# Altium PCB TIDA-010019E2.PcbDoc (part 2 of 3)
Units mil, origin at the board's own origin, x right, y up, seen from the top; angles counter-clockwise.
Board outline 3159.64 x 4813.18 mil, 2 copper layers (Top Layer, Bottom Layer), stack 62 mil thick; 303 components, 177 nets, 861 pads, 1443 vias.
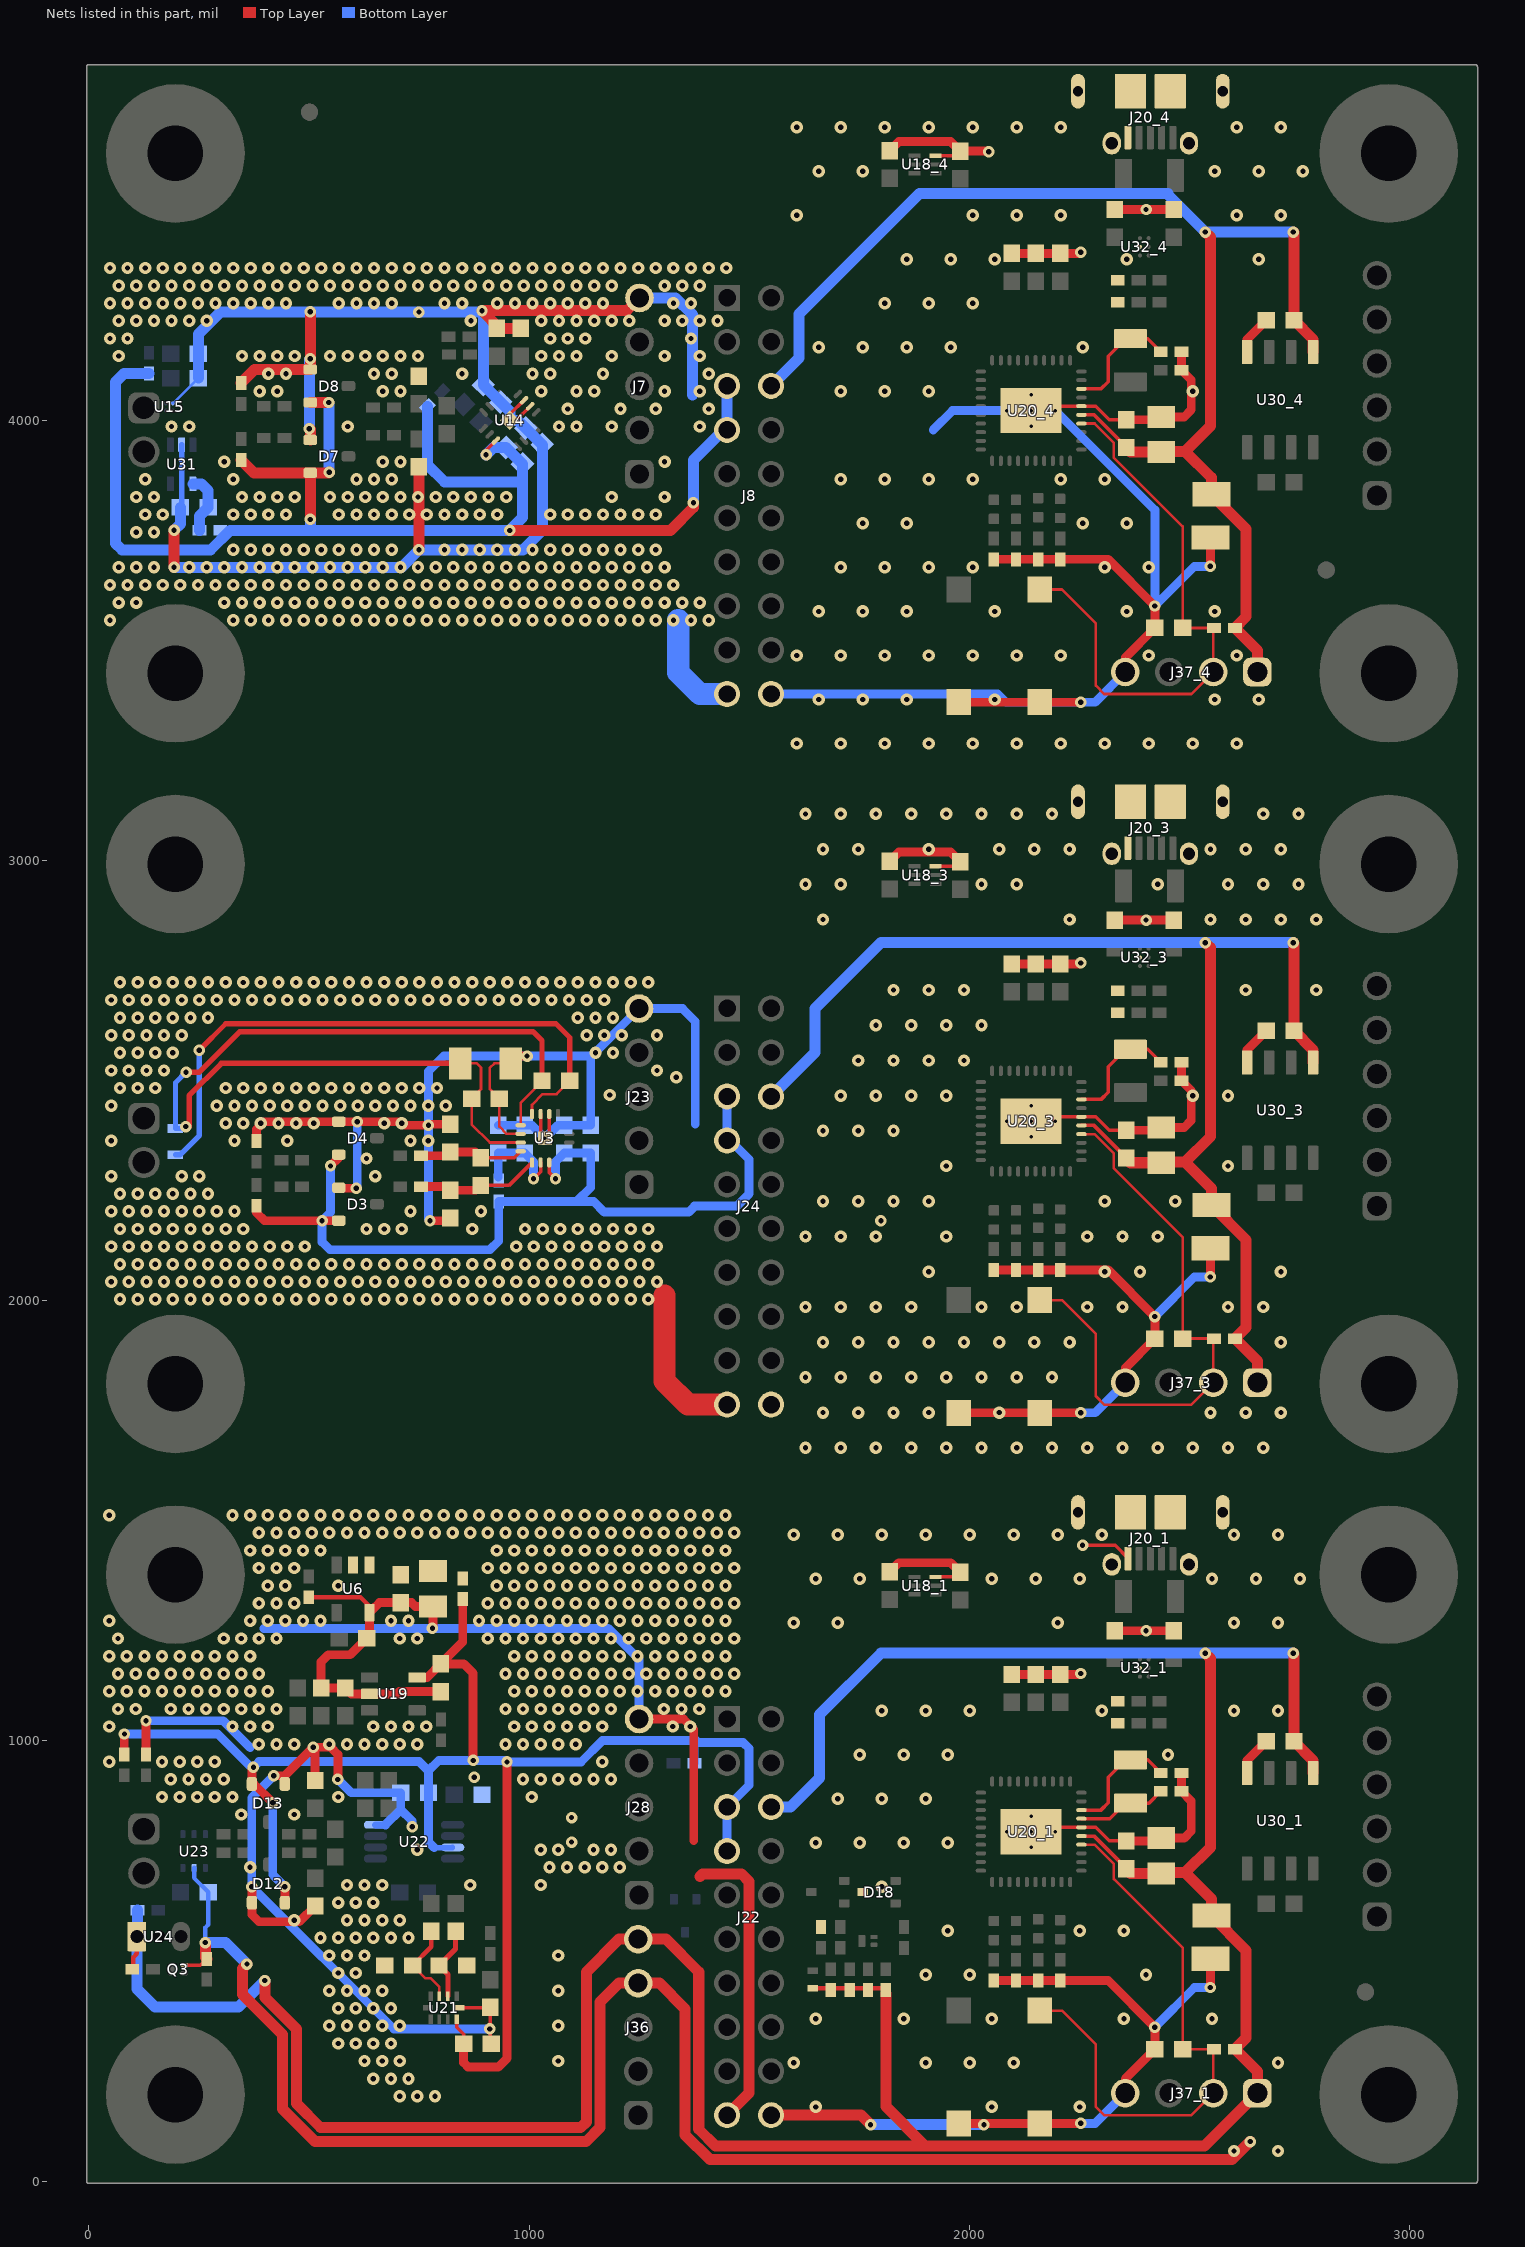
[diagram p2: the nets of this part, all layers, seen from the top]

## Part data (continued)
D16 D17 D18: library part CMP-0028438-2, "Diode, Schottky, 40 V, 0.2 A, SOT-323", Manufacturer="Diodes Inc.", Value1=0.2A, Value2=0.9V
F1_1 F1_3 F1_4: library part CMP-0081903-1, "Fuse, 0.05 A, 60 VDC, SMD", Irating_A=50mA, Manufacturer="Bel Fuse", Supplier Part Number 1=507-1793-1-ND
FID1 FID2 FID3 FID4 FID5 FID6: library part CMP-0077181-1, "Fiducial mark.  There is nothing to buy or mount.", Manufacturer=N/A
H9 H10 H11 H12 H17 H18 H19 H20 H37 H38 H39 H40: library part CMP-0003617-1, "Machine Screw, Round, #4-40 x 1/4, Nylon, Philips panhead", Manufacturer="B&F Fastener Supply", Supplier Part Number 1=H542-ND
H13 H14 H15 H16 H21 H22 H23 H24 H45 H46 H47 H48: library part CMP-0003610-1, "Standoff, Hex, 0.5\"L #4-40 Nylon", Manufacturer=Keystone, Supplier Part Number 1=36-1902C-ND
J2 J5 J31: library part CMP-0082072-1, "Receptacle, 2.54mm, 2x1, Tin, R/A, TH", Color=Green, Current_A=6A, Manufacturer="Wurth Elektronik", Voltage_V=150V
J7 J23 J28 J36: library part CMP-0084909-1, "Header, 2.54mm, 5x1, Gold, TH", Color=Black, Current_A=3A, Manufacturer="Wurth Elektronik", Voltage_V=250V
J8 J22 J24: library part CMP-0054591-2, "Header, 2.54mm, 10x2, Gold, TH", Color=Black, Manufacturer="Sullins Connector Solutions", Supplier Part Number 1=S2011EC-10-ND
J20_1 J20_3 J20_4: library part CMP-0055301-1, "Connector, Receptacle, Micro-USB Type AB, R/A, Bottom Mount SMT", Manufacturer=Molex, Supplier Part Number 1=WM17143CT-ND
J37_1 J37_3 J37_4: library part CMP-0054798-2, "Header, 2.54 mm, 4x1, Gold, TH", Color=Black, Manufacturer="Wurth Elektronik", Supplier Part Number 1=732-5317-ND
J39_1 J39_3 J39_4: library part CMP-0054801-2, "Header, 2.54 mm, 6x1, Gold, TH", Color=Black, Manufacturer="Wurth Elektronik", Supplier Part Number 1=732-5319-ND
LBL1 LBL3 LBL4: library part CMP-0003625-1, "Thermal Transfer Printable Labels, 0.650\" W x 0.200\" H - 10,000 per roll", Manufacturer=Brady, Supplier Part Number 1=97C5133
Logo1 Logo2 Logo16: library part CMP-0074838-1, "Texas Instrument Corporate Signature"
Logo3 Logo5 Logo17: library part CMP-0074847-1, "FCC_disclaimer"
Logo4 Logo6 Logo18: library part CMP-0074769-1
Q3 Q6: library part CMP-0082028-2, "Transistor, NPN, 65 V, 0.1 A, AEC-Q101, 1x0.6mm", Manufacturer="Diodes Inc.", Value1="0.1 A", Value2=450
R4 R9 R44 R50 R70 R85 R120: library part CMP-0026827-3, "RES, 10, 5%, 0.063 W, AEC-Q200 Grade 0, 0402", Manufacturer=Vishay-Dale, Power_W=63mW, Supplier Part Number 1=541-10JCT-ND, TempCo="200 ppm/C", Tolerance_%=5%, Value2=0.063W, Value_Code=10R0, ValueDisplayed=10
R6 R52: library part CMP-0025950-3, "RES, 100 k, 1%, 0.063 W, AEC-Q200 Grade 0, 0402", Manufacturer=Vishay-Dale, Power_W=63mW, Supplier Part Number 1=541-100KLCT-ND, TempCo="100 ppm/C", Tolerance_%=1%, Value2=0.063W, Value_Code=100k
R8: library part CMP-0085900-1, "RES, 1.00 M, 1%, 0.1 W, AEC-Q200 Grade 0, 0603", Manufacturer="Stackpole Electronics Inc", Power_W=100mW, TempCo="100 ppm/C", Tolerance_%=1%, Value2=0.1W, Value_Code=1M00, ValueDisplayed=1.00M
R10 R15 R45 R51 R73 R83: library part CMP-0026245-2, "RES, 2.00 M, 1%, 0.063 W, AEC-Q200 Grade 0, 0402", Manufacturer=Vishay-Dale, Power_W=63mW, Supplier Part Number 1=541-2.00MLCT-ND, TempCo="100 ppm/C", Tolerance_%=1%, Value2=0.063W, Value_Code=2M00, ValueDisplayed=2.00M
R11 R12 R13 R14 R46 R47 R48 R49 R76 R81: library part CMP-0026402-2, "RES, 499, 1%, 0.063 W, AEC-Q200 Grade 0, 0402", Manufacturer=Vishay-Dale, Power_W=63mW, Supplier Part Number 1=541-499LCT-ND, TempCo="100 ppm/C", Tolerance_%=1%, Value2=0.063W, Value_Code=499R, ValueDisplayed=499
R16: library part CMP-0018789-2, "RES, 3.24 k, 0.1%, 0.333 W, 1206", Manufacturer="TT Electronics/IRC", Power_W=333mW, Supplier Part Number 1=66-PFC12L3.24K-B, TempCo="10 ppm/C", Tolerance_%=0.1%, Value2=0.333W, Value_Code=3k24, ValueDisplayed=3.24k
R25_1 R25_3 R25_4: library part CMP-0026935-3, "RES, 47 k, 5%, 0.063 W, AEC-Q200 Grade 0, 0402", Manufacturer=Vishay-Dale, Power_W=63mW, Supplier Part Number 1=541-47KJCT-ND, TempCo="200 ppm/C", Tolerance_%=5%, Value2=0.063W, Value_Code=47k0, ValueDisplayed=47k
R27_1 R27_3 R27_4 R55_1 R55_3 R55_4 R56_1 R56_3 R56_4 R57_1 R57_3 R57_4: library part CMP-0026333-2, "RES, 3.32 k, 1%, 0.063 W, AEC-Q200 Grade 0, 0402", Manufacturer=Vishay-Dale, Power_W=63mW, Supplier Part Number 1=541-3.32KLCT-ND, TempCo="100 ppm/C", Tolerance_%=1%, Value2=0.063W, Value_Code=3k32, ValueDisplayed=3.32k
R65_1 R65_3 R65_4 R66_1 R66_3 R66_4 R109_1 R109_3 R109_4: library part CMP-0022109-5, "RES, 1.00 k, 1%, 0.1 W, AEC-Q200 Grade 0, 0603", Manufacturer=Vishay-Dale, Power_W=100mW, Supplier Part Number 1=541-1.00KHCT-ND, TempCo="100 ppm/C", Tolerance_%=1%, Value2=0.1W, Value_Code=1k00, ValueDisplayed=1.00k
R71: library part CMP-0026938-5, "RES, 4.7 k, 5%, 0.063 W, AEC-Q200 Grade 0, 0402", Manufacturer=Vishay-Dale, Power_W=63mW, Supplier Part Number 1=541-4.7KJCT-ND, TempCo="200 ppm/C", Tolerance_%=5%, Value2=0.063W, Value_Code=4k70, ValueDisplayed=4.7k
R72: library part CMP-0022441-4, "RES, 487 k, 1%, 0.1 W, AEC-Q200 Grade 0, 0603", Manufacturer=Vishay-Dale, Power_W=100mW, Supplier Part Number 1=541-487KHCT-ND, TempCo="100 ppm/C", Tolerance_%=1%, Value2=0.1W, Value_Code=487k
R74 R75 R78 R80: library part CMP-0021998-4, "RES, 10.0 k, 1%, 0.1 W, AEC-Q200 Grade 0, 0603", Manufacturer=Vishay-Dale, Power_W=100mW, Supplier Part Number 1=541-10.0KHCT-ND, TempCo="100 ppm/C", Tolerance_%=1%, Value2=0.1W, Value_Code=10k0, ValueDisplayed=10.0k
R77 R82: library part CMP-0025958-3, "RES, 10.0 k, 1%, 0.063 W, AEC-Q200 Grade 0, 0402", Manufacturer=Vishay-Dale, Power_W=63mW, Supplier Part Number 1=541-10.0KLCT-ND, TempCo="100 ppm/C", Tolerance_%=1%, Value2=0.063W, Value_Code=10k0, ValueDisplayed=10.0k
R79: library part CMP-0022372-4, "RES, 3.09 k, 1%, 0.1 W, AEC-Q200 Grade 0, 0603", Manufacturer=Vishay-Dale, Power_W=100mW, Supplier Part Number 1=541-3.09KHCT-ND, TempCo="100 ppm/C", Tolerance_%=1%, Value2=0.1W, Value_Code=3k09, ValueDisplayed=3.09k
R84: library part CMP-0026915-3, "RES, 39 k, 5%, 0.063 W, AEC-Q200 Grade 0, 0402", Manufacturer=Vishay-Dale, Power_W=63mW, Supplier Part Number 1=541-39KJCT-ND, TempCo="200 ppm/C", Tolerance_%=5%, Value2=0.063W, Value_Code=39k0, ValueDisplayed=39k
R86: library part CMP-0026963-3, "RES, 68 k, 5%, 0.063 W, AEC-Q200 Grade 0, 0402", Manufacturer=Vishay-Dale, Power_W=63mW, Supplier Part Number 1=541-68KJCT-ND, TempCo="200 ppm/C", Tolerance_%=5%, Value2=0.063W, Value_Code=68k0, ValueDisplayed=68k
R87: library part CMP-0026966-5, "RES, 6.8 k, 5%, 0.063 W, AEC-Q200 Grade 0, 0402", Manufacturer=Vishay-Dale, Power_W=63mW, Supplier Part Number 1=541-6.8KJCT-ND, TempCo="200 ppm/C", Tolerance_%=5%, Value2=0.063W, Value_Code=6k80, ValueDisplayed=6.8k
R110: library part CMP-0026193-2, "RES, 249 k, 1%, 0.063 W, AEC-Q200 Grade 0, 0402", Manufacturer=Vishay-Dale, Power_W=63mW, Supplier Part Number 1=541-249KLCT-ND, TempCo="100 ppm/C", Tolerance_%=1%, Value2=0.063W, Value_Code=249k
R111 R112 R113: library part CMP-0026823-3, "RES, 100 k, 5%, 0.063 W, AEC-Q200 Grade 0, 0402", Manufacturer=Vishay-Dale, Power_W=63mW, Supplier Part Number 1=541-100KJCT-ND, TempCo="200 ppm/C", Tolerance_%=5%, Value2=0.063W, Value_Code=100k
R114: library part CMP-0026852-3, "RES, 1.0 k, 5%, 0.063 W, AEC-Q200 Grade 0, 0402", Manufacturer=Vishay-Dale, Power_W=63mW, Supplier Part Number 1=541-1.0KJCT-ND, TempCo="200 ppm/C", Tolerance_%=5%, Value2=0.063W, Value_Code=1k00, ValueDisplayed=1.0k
R115: library part CMP-0026490-2, "RES, 61.9 k, 1%, 0.063 W, AEC-Q200 Grade 0, 0402", Manufacturer=Vishay-Dale, Power_W=63mW, Supplier Part Number 1=541-61.9KLCT-ND, TempCo="100 ppm/C", Tolerance_%=1%, Value2=0.063W, Value_Code=61k9, ValueDisplayed=61.9k
R116_1 R116_3 R116_4 R117_1 R117_3 R117_4 R118_1 R118_3 R118_4 R119_1 R119_3 R119_4 R121: library part CMP-0081856-1, "RES, 0, 0%, 0.2 W, AEC-Q200 Grade 0, 0402", Manufacturer=Vishay-Dale, Power_W=200mW, Supplier Part Number 1=541-0.0YBTR-ND, Tolerance_%=0%, Value2=0.2W, Value_Code=0
RT2: library part CMP-0001709-3, "Temperature Sensor 100 ohm, SMD", Manufacturer=Vishay/Beyschlag, Supplier Part Number 1=PTS0603100CT-ND
S1_1 S1_3 S1_4 S2_1 S2_3 S2_4: library part CMP-0002196-2, "Switch, Tactile, SPST, 12 V, SMD", CurrentRating_mA=50A, Manufacturer="Wurth Elektronik", Supplier Part Number 1=31T8978
SH-J1 SH-J2 SH-J3 SH-J4 SH-J5 SH-J6 SH-J7 SH-J8 SH-J9 SH-J10 SH-J11 SH-J12 SH-J13 SH-J14 SH-J15 SH-J16 SH-J17 SH-J18 SH-J19 SH-J20 SH-J21: library part CMP-0003761-2, "Shunt, 2.54mm, Gold, Black", Manufacturer="Wurth Elektronik", Supplier Part Number 1=732-2678-ND
TP1_1 TP1_3 TP1_4 TP2_1 TP2_3 TP2_4: library part CMP-0003968-1, "Test Point, SMT", Manufacturer=Harwin, Supplier Part Number 1=952-2664-1-ND
U3 U14: library part CMP-0078503-1, "16-Bit, 4-Channel, 2-kSPS, Delta-Sigma ADC with UART Interface, RTE0016D (WQFN-16)", Alternate Manufacturer="Texas Instruments", Alternate PartNumber=ADS112U04IRTER
U6: library part CMP-0082641-1, "Low-Drift Low-Power Small-Footprint Series Voltage Reference With Clean Start, DBV0005A (SOT-23-5)", Alternate Manufacturer="Texas Instruments", Operating Temperature Range="-40 to 125 C", Rating=Catalog
U15: library part CMP-0066231-1, "+/-0.1degC Precision Analog Temperature Sensor, YFQ0004ACAC (DSBGA-4)", Alternate Manufacturer="Texas Instruments", Alternate PartNumber=LMT70YFQT
U18_1 U18_3 U18_4: library part CMP-0036117-3, "250-mA, Ultralow IQ, Fast Transient Response, RF Low-Dropout Linear Regulator,  DSE0006A (WSON-6)", Manufacturer="Texas Instruments", Operating Temperature Range="-40 to 125 C", Rating=Catalog
U19: library part CMP-0065082-2, "700nA, Precision Zero-Drift Amplifier, DBV0005A (SOT-23-5)", Alternate Manufacturer="Texas Instruments", Alternate PartNumber=LPV821DBVT
U20_1 U20_3 U20_4: library part CMP-0081780-1, "Mixed-Signal Microcontroller, RHA0040E (VQFN-40)", Alternate Manufacturer="Texas Instruments", Alternate PartNumber=MSP430FR2355TRHAT, Operating Temperature Range="-40 to 105 C", Rating=Catalog
U21: library part CMP-0065258-3, "Nanopower, Ultra-Small Size, Sensor Monitor with I2C Interface and Alert Output, RUG0010A (X2QFN-10)", Alternate Manufacturer="Texas Instruments", Alternate PartNumber=ADS7142IRUGT
U22: library part CMP-0081218-1, "Micro-Power (50 µA), Zero-Drift, Rail-to-Rail-Out Instrumentation Amplifier, DGK0008A (VSSOP-8)", Alternate Manufacturer="Texas Instruments", Alternate PartNumber=INA317IDGKT
U23: library part CMP-0081990-1, "High-Accuracy, Low-Power, Digital Temperature Sensor With SMBus- and I2C-Compatible Interface, DRV0006B (WSON-6)", Alternate Manufacturer="Texas Instruments", Alternate PartNumber=TMP117AIDRVT, Operating Temperature Range="-55 to 150 C"
U24: library part CMP-0076503-2, "0.5degC Accurate 2-pin Temperature Sensor with a Pulse Train Interface, LPG0002A (TO-92-2)", Alternate Manufacturer="Texas Instruments"
U30_1 U30_3 U30_4: library part CMP-0085670-1, "High Speed, Robust EMC Reinforced Dual-Channel Digital Isolator, D0008B (SOIC-8)", Alternate Manufacturer="Texas Instruments", Alternate PartNumber=ISO7721DR, Operating Temperature Range="-55 to 125 C", Rating=Catalog
U31: library part CMP-0013250-3, "TMP235DCK, DCK0005A (SOT-5)", Manufacturer="Texas Instruments"
U32_1 U32_3 U32_4: library part CMP-0034332-1, "Ultra-Low Power, Low Input Voltage, Current Limited Load Switch, 300 mOhms rDS(On), -40 to 85 degC, 6-pin DSBGA (YZP), Green (RoHS & no Sb/Br)", Adjustable Current Limit(Min)(A)="0.155, 0.07, 0.03", Manufacturer="Texas Instruments"
Y1_1 Y1_3 Y1_4: library part CMP-0078856-1, "Crystal, 32.768 KHz, 20 ppm, SMD", Frequency_Fixed=32.768kHz, Frequency Tolerance="20 ppm", Manufacturer="ECS Inc.", Supplier Part Number 1=XC1617CT-ND
ZZ1: library part CMP-0003616-3
ZZ2: library part CMP-0077236-1
ZZ3: library part CMP-0077237-1
ZZ4: library part CMP-0077238-1

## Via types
v1: diameter 28, hole 12, Top Layer to Bottom Layer, tented both sides, 1305 vias
v2: diameter 26, hole 12, Top Layer to Bottom Layer, tented both sides, 120 vias
v3: diameter 19.68, hole 7.87, Top Layer to Bottom Layer, tented both sides, 17 vias
v4: diameter 26, hole 12, Top Layer to Bottom Layer, 1 vias

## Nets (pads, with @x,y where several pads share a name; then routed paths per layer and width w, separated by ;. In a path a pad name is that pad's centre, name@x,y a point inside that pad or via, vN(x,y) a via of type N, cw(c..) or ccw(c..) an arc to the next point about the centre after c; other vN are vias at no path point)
3.3V_1: C65_1.1 C66_1.1 C86_1.1 C87.1 J22.6 J36.5 J37_1.1 R25_1.2 R84.2 R85.1 R86.2 R110.2 R111.2 R112.2 TP2_1.1 U20_1.5 U24.1 U30_1.1 | length 7580.9
  Top Layer w8: U20_1.5@2254.88,784.1 2283.54,784.1 2356.22,711.42 C66_1.1@2356.22,710.01
  Top Layer w10: R86.2@101.38,481.54 101.38,508.68 109.15,516.46 U24.1@109.15,555.83 ; R84.2@1645,437.91 1807.14,437.91 C87.1@1810.76,434.29
  Top Layer w25: v2(400,455.83) 400,417.46 471.5,345.96 471.5,176.9 526.9,121.5 1117.16,121.5 1130.5,134.84 1130.5,475.54 1204.79,549.83 J36.5@1248,549.83 1310.8,549.83 1385.59,475.04 1385.59,118.03 1423.62,80 1900,80 ; C87.1@1810.76,426.38 1810.76,169.24 1900,80 ; C66_1.1@2356.22,710.01 2366.85,699.38 C65_1.1@2436.22,699.38 2437.87,701.03 2490.28,701.03 ; v2(2536.22,1199.38) 2547.76,1187.84 2547.76,758.51 2490.28,701.03 ; v2(2736.22,1199.38) 2737.72,1197.88 C86_1.1@2737.72,999.38 2781.22,955.87 U30_1.1@2781.22,927.07 ; 1900,80 2534.51,80 J37_1.1@2654.51,200 2654.51,249.11 R25_1.2@2603.62,300 2629.21,325.59 2629.21,524.39 TP2_1.1@2550,603.6 2550,641.31 2490.28,701.03
  Bottom Layer w25: R85.1@110.53,615.83 110.53,557.2 U24.1@109.15,555.83 109.15,436.76 150.09,395.83 340,395.83 v2(400,455.83) ; J22.6@1550,850 1594.17,850 1660,915.83 1660,1060 1799.38,1199.38 v2(2536.22,1199.38) v2(2736.22,1199.38)
3.3V_3: C65_3.1 C66_3.1 C86_3.1 J24.6 J37_3.1 R25_3.2 TP2_3.1 U20_3.5 U30_3.1 | length 3069.7
  Top Layer w8: U20_3.5@2254.88,2398.27 2283.54,2398.27 2356.22,2325.59 C66_3.1@2356.22,2324.18
  Top Layer w25: C66_3.1@2356.22,2324.18 2366.85,2313.55 C65_3.1@2436.22,2313.55 2437.87,2315.2 2490.28,2315.2 ; v2(2536.22,2813.55) 2547.76,2802.02 2547.76,2372.68 2490.28,2315.2 ; J37_3.1@2654.51,1814.17 2654.51,1863.28 R25_3.2@2603.62,1914.17 2629.21,1939.76 2629.21,2138.56 TP2_3.1@2550,2217.77 2550,2255.49 2490.28,2315.2 ; v2(2736.22,2813.55) 2737.72,2812.06 C86_3.1@2737.72,2613.55 2781.22,2570.05 U30_3.1@2781.22,2541.25
  Bottom Layer w25: J24.6@1550,2464.17 1650,2564.17 1650,2664.17 1799.38,2813.55 v2(2536.22,2813.55) v2(2736.22,2813.55)
3.3V_4: C65_4.1 C66_4.1 C86_4.1 J8.6 J37_4.1 R25_4.2 TP2_4.1 U20_4.5 U30_4.1 | length 3143.8
  Top Layer w8: U20_4.5@2254.88,4012.44 2283.54,4012.44 2356.21,3939.76 C66_4.1@2356.21,3938.35
  Top Layer w25: C66_4.1@2356.21,3938.35 2366.84,3927.72 C65_4.1@2436.21,3927.72 2437.87,3929.37 2490.27,3929.37 ; v2(2536.21,4427.72) 2547.75,4416.18 2547.75,3986.85 2490.27,3929.37 ; J37_4.1@2654.51,3428.34 2654.51,3477.45 R25_4.2@2603.62,3528.34 2629.21,3553.93 2629.21,3752.73 TP2_4.1@2549.99,3831.94 2549.99,3869.65 2490.27,3929.37 ; v2(2736.21,4427.72) 2737.71,4426.22 C86_4.1@2737.71,4227.72 2781.21,4184.22 U30_4.1@2781.21,4155.42
  Bottom Layer w25: J8.6@1550,4078.35 1613.27,4141.62 1613.27,4241.62 1887.11,4515.46 2451.02,4515.46 2451.02,4512.91 v2(2536.21,4427.72) v2(2736.21,4427.72)
3.3V_7: C51.1 C54.1 C68.1 D12.2 D13.2 J22.5 J22.7 R4.2 R73.2 R113.2 U19.5 U21.9 U22.7 | length 3827.5
  Top Layer w8: U21.9@835.56,367.5 835.56,350.04 851.5,334.1 C54.1@851.5,312.2
  Top Layer w20: R73.2@80.41,969.45 80.41,1015.23 v2(81.01,1015.83) ; v2(373.99,940.35) 370.6,936.96 D13.2@370.6,902.36 375.17,902.36 v2(418,859.53) ; D12.2@445.4,632.68 v2(445.4,668.93) ; U19.5@745.79,1144.27 768.65,1144.27 C51.1@799.61,1175.22 ; R4.2@849.56,1322.2 849.56,1225.18 C51.1@799.61,1175.22 ; C54.1@851.5,312.2 851.5,269.51 861.73,259.27 930.24,259.27 950.17,279.21 950.17,952.21 v2(950,952.38) ; v2(873.04,955.83) 873.04,1154 851.82,1175.22 C51.1@799.61,1175.22
  Bottom Layer w12: 784.61,757.64 825.72,757.64 U22.7@826.41,758.32
  Bottom Layer w20: v2(81.01,1015.83) 293.05,1015.83 368.53,940.35 v2(373.99,940.35) 386.71,953.07 750.76,953.07 771.5,932.33 ; v2(418,859.53) 418,696.33 v2(445.4,668.93) ; 784.61,757.64 771.5,770.75 C68.1@771.5,882.52 771.5,932.33 ; R113.2@1375.53,949.65 1375.53,996.41 ; J22.7@1450,750 J22.5@1450,850 1500,900 1500,983 1486.59,996.41 1375.53,996.41 ; 771.5,932.33 794.99,955.83 v2(873.04,955.83) 946.55,955.83 v2(950,952.38) 1118.18,952.38 1166.69,1000.89 1380,1000.89 1375.53,996.41
3.3V_8: C10.1 C11.1 D3.2 D4.2 J24.5 J24.7 R9.2 R10.2 U3.11 | length 2067.6
  Top Layer w8: U3.11@1046.02,2314.13 1046.02,2291.41 v2(1060.18,2277.25)
  Top Layer w20: R10.2@381.06,2215.78 381.06,2200.34 399.4,2182 v2(530,2182) D3.2@567.75,2182 ; v2(549.05,2306.41) 567.75,2325.11 D4.2@567.75,2332
  Bottom Layer w20: v2(549.05,2306.41) 549.05,2201.06 v2(530,2182) 530,2133.63 547.8,2115.83 911.06,2115.83 931.06,2135.83 R9.2@931.06,2225.78 1108.71,2225.78 ; v2(1060.18,2277.25) 1060.18,2315.75 C11.1@1080.18,2335.75 C10.1@1140.18,2335.75 1140.18,2257.25 1108.71,2225.78 ; J24.7@1450,2364.17 J24.7@1450,2370.8 ; J24.5@1450,2464.17 J24.7@1450,2370.8 ; 1108.71,2225.78 1146.49,2225.78 1170.87,2201.41 1362.53,2201.41 1376.18,2215.06 1471.83,2215.06 1500,2243.23 1500,2320.8 J24.7@1450,2370.8
3.3V_11: C38.1 C39.1 D7.2 D8.2 J8.5 J8.7 R44.2 R45.2 R50.2 R120.2 U14.11 | length 3342
  Top Layer w8: v2(902.51,3921.65) 902.51,3931.95 U14.11@924.63,3954.07
  Top Layer w25: R45.2@346.01,3910.08 375.34,3880.76 D7.2@503.11,3880.76 ; v2(503.11,3774.88) D7.2@503.11,3880.76 ; D8.2@503.11,4040.6 v2(545.15,4040.6) ; v2(546.42,3882.28) 544.89,3880.76 D7.2@503.11,3880.76 ; v2(956,3750) 1321.02,3750 1373.57,3802.54 v2(1373.57,3812.65)
  Bottom Layer w25: R50.2@136.85,4106.27 79.89,4106.27 61.02,4087.4 61.02,3720.16 75.19,3706 277.02,3706 321.02,3750 501.02,3750 ; v2(503.11,3774.88) 503.11,3752.09 501.02,3750 ; v2(545.15,4040.6) 545.15,3883.56 v2(546.42,3882.28) ; R44.2@769.46,4031.63 769.46,3898.66 808.54,3859.57 985.4,3859.57 ; v2(902.51,3921.65) 919.09,3938.23 C39.1@947.81,3938.23 C38.1@985.4,3900.64 985.4,3859.57 ; v2(1373.57,3812.65) 1373.57,3910 1441.91,3978.35 J8.7@1450,3978.35 J8.5@1450,4078.35 ; 501.02,3750 v2(956,3750) 985.4,3779.4 985.4,3859.57
GND_1: C21_1.2 C22_1.2 C23_1.2 C34_1.2 C65_1.2 C66_1.2 C74.2 C83_1.2 C84_1.2 C86_1.2 C88.2 C89_1.2 D18.3 J20_1.5 J20_1.6 J20_1.7 J20_1.8 J20_1.9 J20_1.10 J20_1.11 J22.20 J36.4 J37_1.4 Q3.2 R27_1.1 R55_1.1 R56_1.1 R57_1.1 R65_1.1 R66_1.1 R87.1 R109_1.1 R118_1.1 R119_1.1 S1_1.1 S2_1.1 TP1_1.1 U18_1.3 U20_1.6 U20_1.41 U23.2 U30_1.4 U32_1.B1 | length 6644.5
  Top Layer w8: Q3.2@216.91,490.39 253.24,490.39 R87.1@268,505.16 ; U18_1.3@1923.07,1372.59 1968.74,1372.59 C84_1.2@1979.45,1383.3 ; v3(2140.71,793.94) 2150.55,803.78 U20_1.6@2254.88,803.78 2287.21,803.78 2317.99,773 C66_1.2@2356.22,773 ; v2(2257.57,1444.41) 2331.54,1444.41 2360.32,1415.64 J20_1.5@2360.32,1414.06
  Top Layer w20: C83_1.2@1819.45,1384.4 1840,1404.95 1957.8,1404.95 C84_1.2@1979.45,1383.3 ; S2_1.1@1976.22,131.43 S1_1.1@2160.39,131.43 v2(2253.18,131.43) ; R57_1.1@2056.06,455.95 R56_1.1@2106.22,455.95 R55_1.1@2156.46,455.95 R27_1.1@2206.46,455.95 2315.66,455.95 v2(2421.72,349.88) C21_1.2@2421.72,300 2354.51,232.79 J37_1.4@2354.51,200 ; R66_1.1@2096.38,1150.87 R65_1.1@2151.54,1150.87 2250.68,1150.87 v2(2253.18,1153.38) ; C89_1.2@2330.28,1250.6 v2(2401.67,1250.6) C34_1.2@2464.55,1250.6 ; C66_1.2@2356.22,773 2429.84,773 C65_1.2@2436.22,779.38 2488.28,779.38 2504.51,795.61 2504.51,863.45 C23_1.2@2482.36,885.6 C22_1.2@2482.36,927.33 ; v2(2547.76,440) TP1_1.1@2547.76,505.44 ; U30_1.4@2631.22,927.07 2631.22,955.87 C86_1.2@2674.72,999.38
  Top Layer w25: v2(264.84,542.05) 264.84,508.31 R87.1@268,505.16 ; v2(359.28,493.35) 349.33,483.39 349.33,424.3 440.5,333.12 440.5,164.06 514.06,90.5 1130,90.5 1161.5,122 1161.5,406.68 1204.64,449.83 J36.4@1248,449.83 1296.32,449.83 1354.59,391.56 1354.59,105.19 1410.78,49 2597.27,49 v2(2638.27,90) ; J22.20@1550,150 1754.47,150 v2(1775.94,128.54)
  Bottom Layer w10: U23.2@239.25,711.61 239.25,689.02 C74.2@271.5,656.78 271.5,582.94 264.84,576.29 v2(264.84,542.05)
  Bottom Layer w20: v2(2253.18,131.43) 2285.94,131.43 J37_1.4@2354.51,200 ; v2(2421.72,349.88) 2511.84,440 v2(2547.76,440)
  Bottom Layer w25: v2(264.84,542.05) 310.58,542.05 v2(359.28,493.35) ; v2(1775.94,128.54) v2(2033.41,128.54)
  other v1: 2601.39,68.77 2701.39,68.77 1651.39,168.77 2051.39,168.77 2251.39,168.77 1601.39,268.77 1901.39,268.77 2001.39,268.77 2101.39,268.77 2701.39,268.77 1651.39,368.77 1851.39,368.77 2051.39,368.77 2351.39,368.77 2551.39,368.77 1901.39,468.77 2001.39,468.77 2401.39,468.77 1951.39,568.77 2251.39,568.77 2351.39,568.77 1801.39,668.77 1651.39,768.77 1751.39,768.77 1851.39,768.77 1951.39,768.77 1701.39,868.77 1801.39,868.77 1901.39,868.77 1751.39,968.77 1851.39,968.77 1951.39,968.77 2451.39,968.77 1801.39,1068.77 1901.39,1068.77 2001.39,1068.77 2301.39,1068.77 2601.39,1068.77 2701.39,1068.77 1601.39,1268.77 1701.39,1268.77 2201.39,1268.77 2601.39,1268.77 2701.39,1268.77 1651.39,1368.77 1751.39,1368.77 2051.39,1368.77 2151.39,1368.77 2251.39,1368.77 2551.39,1368.77 2651.39,1368.77 2751.39,1368.77 1601.39,1468.77 1701.39,1468.77 1801.39,1468.77 1901.39,1468.77 2001.39,1468.77 2101.39,1468.77 2201.39,1468.77 2301.39,1468.77 2601.39,1468.77 2701.39,1468.77
  other v3: 2140.71,758.51 2085.59,793.94 2195.83,793.94 2140.71,829.37
GND_3: C21_3.2 C22_3.2 C23_3.2 C34_3.2 C65_3.2 C66_3.2 C83_3.2 C84_3.2 C86_3.2 C89_3.2 J20_3.5 J20_3.6 J20_3.7 J20_3.8 J20_3.9 J20_3.10 J20_3.11 J24.20 J37_3.4 R27_3.1 R55_3.1 R56_3.1 R57_3.1 R65_3.1 R66_3.1 R109_3.1 R118_3.1 R119_3.1 S1_3.1 S2_3.1 TP1_3.1 U18_3.3 U20_3.6 U20_3.41 U30_3.4 U32_3.B1 | length 2374.4
  Top Layer w8: U18_3.3@1923.07,2986.76 1968.74,2986.76 C84_3.2@1979.45,2997.47 ; v3(2140.71,2408.11) 2150.55,2417.96 U20_3.6@2254.88,2417.96 2287.21,2417.96 2317.99,2387.17 C66_3.2@2356.22,2387.17
  Top Layer w20: C83_3.2@1819.45,2998.57 1840,3019.12 1957.8,3019.12 C84_3.2@1979.45,2997.47 ; S2_3.1@1976.22,1745.6 S1_3.1@2160.39,1745.6 v2(2253.18,1745.6) ; R57_3.1@2056.06,2070.12 R56_3.1@2106.22,2070.12 R55_3.1@2156.46,2070.12 R27_3.1@2206.46,2070.12 2315.66,2070.12 v2(2421.72,1964.06) C21_3.2@2421.72,1914.17 2354.51,1846.96 J37_3.4@2354.51,1814.17 ; R66_3.1@2096.38,2765.05 R65_3.1@2151.54,2765.05 2250.68,2765.05 v2(2253.18,2767.55) ; C89_3.2@2330.28,2864.77 v2(2401.67,2864.77) C34_3.2@2464.55,2864.77 ; C66_3.2@2356.22,2387.17 2429.84,2387.17 C65_3.2@2436.22,2393.55 2488.28,2393.55 2504.51,2409.79 2504.51,2477.62 C23_3.2@2482.36,2499.77 C22_3.2@2482.36,2541.5 ; v2(2547.76,2054.17) TP1_3.1@2547.76,2119.61 ; U30_3.4@2631.22,2541.25 2631.22,2570.05 C86_3.2@2674.72,2613.55
  Bottom Layer w20: v2(2253.18,1745.6) 2285.94,1745.6 J37_3.4@2354.51,1814.17 ; v2(2421.72,1964.06) 2511.84,2054.17 v2(2547.76,2054.17)
  other v1: 1628,1666 1708,1666 1788,1666 1868,1666 1948,1666 2028,1666 2108,1666 2188,1666 2268,1666 2348,1666 2428,1666 2508,1666 2588,1666 2668,1666 1668,1746 1748,1746 1828,1746 1908,1746 2068,1746 2548,1746 2628,1746 2708,1746 1628,1826 1708,1826 1788,1826 1868,1826 1948,1826 2028,1826 2108,1826 2188,1826 1668,1906 1748,1906 1828,1906 1908,1906 1988,1906 2068,1906 2148,1906 2228,1906 2708,1906 1628,1986 1708,1986 1788,1986 1868,1986 2028,1986 2108,1986 2268,1986 2348,1986 2588,1986 2668,1986 1908,2066 2308,2066 2388,2066 2708,2066 1628,2146 1708,2146 1788,2146 1948,2146 2268,2146 2348,2146 2428,2146 1668,2226 1748,2226 1828,2226 1908,2226 2308,2226 2468,2226 1948,2306 2588,2306 1668,2386 1748,2386 1828,2386 1708,2466 1788,2466 1868,2466 1948,2466 2508,2466 2588,2466 1748,2546 1828,2546 1908,2546 1988,2546 1788,2626 1868,2626 1948,2626 2028,2626 1828,2706 1908,2706 1988,2706 2628,2706 2788,2706 1668,2866 2228,2866 2548,2866 2628,2866 2708,2866 2788,2866 1628,2946 1708,2946 2028,2946 2108,2946 2428,2946 2588,2946 2668,2946 2748,2946 1668,3026 1748,3026 1908,3026 2068,3026 2148,3026 2228,3026 2548,3026 2628,3026 2708,3026 1628,3106 1708,3106 1788,3106 1868,3106 1948,3106 2028,3106 2108,3106 2188,3106 2668,3106 2748,3106
  other v2: 1799.38,2181.55
  other v3: 2140.71,2372.68 2085.59,2408.11 2195.83,2408.11 2140.71,2443.55
GND_4: C21_4.2 C22_4.2 C23_4.2 C34_4.2 C65_4.2 C66_4.2 C83_4.2 C84_4.2 C86_4.2 C89_4.2 J8.20 J20_4.5 J20_4.6 J20_4.7 J20_4.8 J20_4.9 J20_4.10 J20_4.11 J37_4.4 R27_4.1 R55_4.1 R56_4.1 R57_4.1 R65_4.1 R66_4.1 R109_4.1 R118_4.1 R119_4.1 S1_4.1 S2_4.1 TP1_4.1 U18_4.3 U20_4.6 U20_4.41 U30_4.4 U32_4.B1 | length 3873.8
  Top Layer w8: U18_4.3@1923.06,4600.93 1968.73,4600.93 C84_4.2@1979.44,4611.64 ; v3(2140.7,4022.28) 2150.54,4032.12 U20_4.6@2254.88,4032.12 2287.2,4032.12 2317.99,4001.34 C66_4.2@2356.21,4001.34
  Top Layer w20: C83_4.2@1819.44,4612.74 1839.99,4633.29 1957.79,4633.29 C84_4.2@1979.44,4611.64 2042.61,4611.64 v2(2044.25,4610) ; S2_4.1@1976.21,3359.77 S1_4.1@2160.39,3359.77 v2(2253.17,3359.77) ; R57_4.1@2056.06,3684.29 R56_4.1@2106.21,3684.29 R55_4.1@2156.45,3684.29 R27_4.1@2206.45,3684.29 2315.65,3684.29 v2(2421.72,3578.22) C21_4.2@2421.72,3528.34 2354.51,3461.13 J37_4.4@2354.51,3428.34 ; R66_4.1@2096.37,4379.22 R65_4.1@2151.53,4379.22 2250.67,4379.22 v2(2253.17,4381.72) ; C89_4.2@2330.28,4478.94 v2(2401.67,4478.94) C34_4.2@2464.54,4478.94 ; C66_4.2@2356.21,4001.34 2429.84,4001.34 C65_4.2@2436.21,4007.72 2488.27,4007.72 2504.51,4023.96 2504.51,4091.79 C23_4.2@2482.35,4113.94 C22_4.2@2482.35,4155.67 ; v2(2547.75,3668.34) TP1_4.1@2547.75,3733.78 ; U30_4.4@2631.21,4155.42 2631.21,4184.22 C86_4.2@2674.72,4227.72
  Bottom Layer w20: J8.20@1550,3378.35 2064.9,3378.35 2083.48,3359.77 v2(2253.17,3359.77) 2285.93,3359.77 J37_4.4@2354.51,3428.34 ; 1918.39,3978.35 1962.33,4022.28 v3(2085.58,4022.28) ; v3(2195.82,4022.28) 2421.72,3796.38 v2(2421.72,3578.22) 2511.84,3668.34 v2(2547.75,3668.34)
  other v1: 1608,3266 1708,3266 1808,3266 1908,3266 2008,3266 2108,3266 2208,3266 2308,3266 2408,3266 2508,3266 2608,3266 1658,3366 1758,3366 1858,3366 2058,3366 2558,3366 2658,3366 1608,3466 1708,3466 1808,3466 1908,3466 2008,3466 2108,3466 2208,3466 2408,3466 2608,3466 1658,3566 1758,3566 1858,3566 2058,3566 2358,3566 2558,3566 1708,3666 1808,3666 1908,3666 2008,3666 2308,3666 2408,3666 1758,3766 1858,3766 2258,3766 2358,3766 1708,3866 1808,3866 1908,3866 2008,3866 2208,3866 2308,3866 1708,4066 1808,4066 1908,4066 2508,4066 1658,4166 1758,4166 1858,4166 1958,4166 2258,4166 1808,4266 1908,4266 2008,4266 1858,4366 1958,4366 2058,4366 2358,4366 2658,4366 1608,4466 2008,4466 2108,4466 2208,4466 2608,4466 2708,4466 1658,4566 1758,4566 2558,4566 2658,4566 2758,4566 1608,4666 1708,4666 1808,4666 1908,4666 2008,4666 2108,4666 2208,4666 2608,4666 2708,4666
  other v3: 2140.7,3986.85 2140.7,4057.72
GND_7: C1.2 C2.2 C6.2 C7.2 C9.2 C51.2 C53.2 C54.2 C67.2 C68.2 C69.1 C72.2 C73.2 D12.1 D13.1 J22.19 J28.5 R6.1 R72.1 R83.1 U6.5 U19.2 U21.10 U22.4 | length 5277.9
  Top Layer w8: U21.10@841.96,394.07 910.69,394.07 C67.2@911.54,394.92 v2@911.54,345.83 ; v2(910.64,345.83) v2@911.54,345.83 ; C54.2@914.49,312.2 911.54,315.16 v2@911.54,345.83
  Top Layer w10: R6.1@499.56,1326.49 617.22,1326.49 U6.5@644.83,1298.88
  Top Layer w20: R83.1@130,969.45 v2(130,1045.83) ; v2(370,669.09) 370.6,668.5 D12.1@370.6,632.68 370.6,605.32 386.71,589.21 477.98,589.21 C69.1@514.06,625.28 ; v2(420,921.06) 445.23,921.06 v2(510,985.83) ; C73.2@514.06,910.23 514.06,981.77 v2(510,985.83) ; v2(565.79,912.74) 565.79,969.39 549.35,985.83 v2(510,985.83) ; v2(734.5,805.44) v2@735.53,806.46 ; v2(780.7,1255.83) 782.08,1257.2 C6.2@782.08,1305.83 741.53,1305.83 733.02,1314.33 C7.2@708.26,1314.33 660.27,1314.33 644.83,1298.88 U6.5@637.64,1291.69 637.64,1239.53 C9.2@631.73,1233.62 593.93,1195.83 543.73,1195.83 527.8,1179.89 R72.1@527.8,1120.28 C53.2@582.92,1120.28 596.33,1106.87 U19.2@637.52,1106.87 700,1106.87 705.36,1112.23 C51.2@799.61,1112.23 ; J28.5@1250,1049.83 1350.9,1049.83 1374.28,1026.45 1374.28,773.36
  Top Layer w25: 1388,691.83 1394.2,698.03 1483.26,698.03 1500,681.29 1500,200 J22.19@1450,150
  Bottom Layer w16: U22.4@651.21,809.51 U22.4@673.78,809.51
  Bottom Layer w20: v2(130,1045.83) 305.28,1045.83 366.57,984.53 ; 398,1255.83 v2(780.7,1255.83) 1180,1255.83 1250,1185.83 J28.5@1250,1049.83 ; v2(420,921.06) 370,871.06 v2(370,669.09) 693.27,345.83 v2(910.64,345.83) ; v2(510,985.83) 510,979.07 v2@514.06,979.07 ; v2(565.79,912.74) 596,882.52 C68.2@708.5,882.52 708.5,844.23 ; U22.4@673.78,809.51 708.5,844.23 ; v2(734.5,805.44) 734.5,818.23 708.5,844.23
  other v1: 706.42,192.87 746.42,192.87 786.42,192.87 646.42,232.87 686.42,232.87 726.42,232.87 626.42,272.87 666.42,272.87 706.42,272.87 1066.42,272.87 566.42,312.87 606.42,312.87 646.42,312.87 686.42,312.87 546.42,352.87 586.42,352.87 626.42,352.87 666.42,352.87 706.42,352.87 1066.42,352.87 566.42,392.87 606.42,392.87 646.42,392.87 686.42,392.87 546.42,432.87 586.42,432.87 626.42,432.87 666.42,432.87 1066.42,432.87 566.42,472.87 606.42,472.87 546.42,512.87 586.42,512.87 626.42,512.87 1066.42,512.87 526.42,552.87 566.42,552.87 606.42,552.87 646.42,552.87 686.42,552.87 726.42,552.87 466.42,592.87 586.42,592.87 626.42,592.87 666.42,592.87 706.42,592.87 566.42,632.87 606.42,632.87 646.42,632.87 586.42,672.87 626.42,672.87 666.42,672.87 866.42,672.87 1026.42,672.87 366.42,712.87 1046.42,712.87 1086.42,712.87 1126.42,712.87 1166.42,712.87 1206.42,712.87 746.42,752.87 1026.42,752.87 1066.42,752.87 1146.42,752.87 1186.42,752.87 346.42,832.87 466.42,832.87 166.42,872.87 206.42,872.87 246.42,872.87 286.42,872.87 326.42,872.87 566.42,872.87 1006.42,872.87 186.42,912.87 226.42,912.87 266.42,912.87 306.42,912.87 986.42,912.87 1026.42,912.87 1066.42,912.87 1106.42,912.87 1146.42,912.87 1186.42,912.87 46.42,952.87 166.42,952.87 206.42,952.87 246.42,952.87 286.42,952.87 1166.42,952.87 386.42,992.87 426.42,992.87 466.42,992.87 546.42,992.87 586.42,992.87 626.42,992.87 666.42,992.87 706.42,992.87 746.42,992.87 946.42,992.87 986.42,992.87 1026.42,992.87 1066.42,992.87 1106.42,992.87 46.42,1032.87 326.42,1032.87 366.42,1032.87 406.42,1032.87 646.42,1032.87 686.42,1032.87 726.42,1032.87 766.42,1032.87 966.42,1032.87 1006.42,1032.87 1046.42,1032.87 1086.42,1032.87 1126.42,1032.87 1166.42,1032.87 1326.42,1032.87 1366.42,1032.87 66.42,1072.87 106.42,1072.87 186.42,1072.87 226.42,1072.87 266.42,1072.87 306.42,1072.87 346.42,1072.87 386.42,1072.87 426.42,1072.87 946.42,1072.87 986.42,1072.87 1026.42,1072.87 1066.42,1072.87 1106.42,1072.87 1146.42,1072.87 1186.42,1072.87 1306.42,1072.87 1346.42,1072.87 1386.42,1072.87 46.42,1112.87 86.42,1112.87 126.42,1112.87 166.42,1112.87 206.42,1112.87 246.42,1112.87 286.42,1112.87 326.42,1112.87 366.42,1112.87 406.42,1112.87 966.42,1112.87 1006.42,1112.87 1046.42,1112.87 1086.42,1112.87 1126.42,1112.87 1166.42,1112.87 1206.42,1112.87 1246.42,1112.87 1286.42,1112.87 1326.42,1112.87 1366.42,1112.87 1406.42,1112.87 1446.42,1112.87 66.42,1152.87 106.42,1152.87 146.42,1152.87 186.42,1152.87 226.42,1152.87 266.42,1152.87 306.42,1152.87 346.42,1152.87 386.42,1152.87 946.42,1152.87 986.42,1152.87 1026.42,1152.87 1066.42,1152.87 1106.42,1152.87 1146.42,1152.87 1186.42,1152.87 1226.42,1152.87 1266.42,1152.87 1306.42,1152.87 1346.42,1152.87 1386.42,1152.87 1426.42,1152.87 1466.42,1152.87 46.42,1192.87 86.42,1192.87 126.42,1192.87 166.42,1192.87 206.42,1192.87 246.42,1192.87 286.42,1192.87 326.42,1192.87 366.42,1192.87 966.42,1192.87 1006.42,1192.87 1046.42,1192.87 1086.42,1192.87 1126.42,1192.87 1166.42,1192.87 1206.42,1192.87 1246.42,1192.87 1286.42,1192.87 1326.42,1192.87 1366.42,1192.87 1406.42,1192.87 1446.42,1192.87 66.42,1232.87 306.42,1232.87 346.42,1232.87 386.42,1232.87 426.42,1232.87 706.42,1232.87 746.42,1232.87 906.42,1232.87 946.42,1232.87 986.42,1232.87 1026.42,1232.87 1066.42,1232.87 1106.42,1232.87 1146.42,1232.87 1186.42,1232.87 1226.42,1232.87 1266.42,1232.87 1306.42,1232.87 1346.42,1232.87 1386.42,1232.87 1426.42,1232.87 1466.42,1232.87 46.42,1272.87 366.42,1272.87 406.42,1272.87 446.42,1272.87 486.42,1272.87 526.42,1272.87 686.42,1272.87 726.42,1272.87 886.42,1272.87 926.42,1272.87 966.42,1272.87 1006.42,1272.87 1046.42,1272.87 1086.42,1272.87 1126.42,1272.87 1166.42,1272.87 1206.42,1272.87 1246.42,1272.87 1286.42,1272.87 1326.42,1272.87 1366.42,1272.87 1406.42,1272.87 1446.42,1272.87 386.42,1312.87 426.42,1312.87 466.42,1312.87 906.42,1312.87 946.42,1312.87 986.42,1312.87 1026.42,1312.87 1066.42,1312.87 1106.42,1312.87 1146.42,1312.87 1186.42,1312.87 1226.42,1312.87 1266.42,1312.87 1306.42,1312.87 1346.42,1312.87 1386.42,1312.87 1426.42,1312.87 1466.42,1312.87 406.42,1352.87 446.42,1352.87 566.42,1352.87 926.42,1352.87 966.42,1352.87 1006.42,1352.87 1046.42,1352.87 1086.42,1352.87 1126.42,1352.87 1166.42,1352.87 1206.42,1352.87 1246.42,1352.87 1286.42,1352.87 1326.42,1352.87 1366.42,1352.87 1406.42,1352.87 1446.42,1352.87 386.42,1392.87 426.42,1392.87 466.42,1392.87 906.42,1392.87 946.42,1392.87 986.42,1392.87 1026.42,1392.87 1066.42,1392.87 1106.42,1392.87 1146.42,1392.87 1186.42,1392.87 1226.42,1392.87 1266.42,1392.87 1306.42,1392.87 1346.42,1392.87 1386.42,1392.87 1426.42,1392.87 1466.42,1392.87 366.42,1432.87 406.42,1432.87 446.42,1432.87 486.42,1432.87 526.42,1432.87 926.42,1432.87 966.42,1432.87 1006.42,1432.87 1046.42,1432.87 1086.42,1432.87 1126.42,1432.87 1166.42,1432.87 1206.42,1432.87 1246.42,1432.87 1286.42,1432.87 1326.42,1432.87 1366.42,1432.87 1406.42,1432.87 1446.42,1432.87 386.42,1472.87 426.42,1472.87 466.42,1472.87 506.42,1472.87 546.42,1472.87 586.42,1472.87 626.42,1472.87 666.42,1472.87 706.42,1472.87 746.42,1472.87 786.42,1472.87 826.42,1472.87 866.42,1472.87 906.42,1472.87 946.42,1472.87 986.42,1472.87 1026.42,1472.87 1066.42,1472.87 1106.42,1472.87 1146.42,1472.87 1186.42,1472.87 1226.42,1472.87 1266.42,1472.87 1306.42,1472.87 1346.42,1472.87 1386.42,1472.87 1426.42,1472.87 1466.42,1472.87 46.42,1512.87 326.42,1512.87 366.42,1512.87 406.42,1512.87 446.42,1512.87 486.42,1512.87 526.42,1512.87 566.42,1512.87 606.42,1512.87 646.42,1512.87 686.42,1512.87 726.42,1512.87 766.42,1512.87 806.42,1512.87 846.42,1512.87 886.42,1512.87 926.42,1512.87 966.42,1512.87 1006.42,1512.87 1046.42,1512.87 1086.42,1512.87 1126.42,1512.87 1166.42,1512.87 1206.42,1512.87 1246.42,1512.87 1286.42,1512.87 1326.42,1512.87 1366.42,1512.87 1406.42,1512.87 1446.42,1512.87
  other v2: 1096.6,770.42 1096.6,826.11 875.43,917.94
GND_8: C10.2 C11.2 C12.2 C13.2 C14.2 C17.2 C18.2 D3.1 D4.1 J23.5 J24.19 R15.1 R16.1 U3.2 U3.3 U3.6 U3.17 | length 3122.4
  Top Layer w6: R16.1@958.15,2539.41 921.06,2539.41 911.06,2529.41 911.06,2480.9 C18.2@932.56,2459.41 932.56,2395.41 948.88,2379.09 U3.6@981.06,2379.09
  Top Layer w8: U3.3@1026.34,2424.37 1026.34,2379.09 v3(1036.18,2369.25) 1046.02,2379.09 U3.2@1046.02,2424.37
  Top Layer w20: R15.1@381.06,2363.03 381.06,2389.84 398.03,2406.81 D4.1@567.75,2406.81 v2(610,2406.81) 711.31,2406.81 719.17,2398.95 v2(771.5,2398.95) 773.45,2400.9 C17.2@821.06,2400.9 ; D3.1@567.75,2256.81 568.73,2255.83 v2(607.54,2255.83) ; v2(775.05,2182) 815.15,2182 C14.2@821.06,2187.91 ; R16.1@958.15,2539.41 974.57,2555.83 v2(995.55,2555.83)
  Top Layer w50: 1308,2011.83 1308,1817.26 1361.09,1764.17 J24.19@1450,1764.17
  Bottom Layer w20: v2(607.54,2255.83) 610,2258.29 v2(610,2406.81) ; v2(775.05,2182) 771.5,2185.55 v2(771.5,2398.95) 771.5,2520.75 806.57,2555.83 v2(995.55,2555.83) 1142,2555.83 J23.5@1250,2663.83 1348.35,2663.83 1377.72,2634.46 1377.72,2401.43 ; C12.2@930.18,2398.74 C13.2@990.18,2398.74 1006.68,2398.74 v3(1036.18,2369.25) 1065.67,2398.74 C11.2@1080.18,2398.74 C10.2@1140.18,2398.74 1140.18,2546.68
  other v1: 70.93,2003.23 110.93,2003.23 150.93,2003.23 190.93,2003.23 230.93,2003.23 270.93,2003.23 310.93,2003.23 350.93,2003.23 390.93,2003.23 430.93,2003.23 470.93,2003.23 510.93,2003.23 550.93,2003.23 590.93,2003.23 630.93,2003.23 670.93,2003.23 710.93,2003.23 750.93,2003.23 790.93,2003.23 830.93,2003.23 870.93,2003.23 910.93,2003.23 950.93,2003.23 990.93,2003.23 1030.93,2003.23 1070.93,2003.23 1110.93,2003.23 1150.93,2003.23 1190.93,2003.23 1230.93,2003.23 1270.93,2003.23 50.93,2043.23 90.93,2043.23 130.93,2043.23 170.93,2043.23 210.93,2043.23 250.93,2043.23 290.93,2043.23 330.93,2043.23 370.93,2043.23 410.93,2043.23 450.93,2043.23 490.93,2043.23 530.93,2043.23 570.93,2043.23 610.93,2043.23 650.93,2043.23 690.93,2043.23 730.93,2043.23 770.93,2043.23 810.93,2043.23 850.93,2043.23 890.93,2043.23 930.93,2043.23 970.93,2043.23 1010.93,2043.23 1050.93,2043.23 1090.93,2043.23 1130.93,2043.23 1170.93,2043.23 1210.93,2043.23 1250.93,2043.23 1290.93,2043.23 70.93,2083.23 110.93,2083.23 150.93,2083.23 190.93,2083.23 230.93,2083.23 270.93,2083.23 310.93,2083.23 350.93,2083.23 390.93,2083.23 430.93,2083.23 470.93,2083.23 510.93,2083.23 550.93,2083.23 590.93,2083.23 630.93,2083.23 670.93,2083.23 710.93,2083.23 750.93,2083.23 790.93,2083.23 830.93,2083.23 870.93,2083.23 910.93,2083.23 950.93,2083.23 990.93,2083.23 1030.93,2083.23 1070.93,2083.23 1110.93,2083.23 1150.93,2083.23 1190.93,2083.23 1230.93,2083.23 1270.93,2083.23 50.93,2123.23 90.93,2123.23 130.93,2123.23 170.93,2123.23 210.93,2123.23 250.93,2123.23 290.93,2123.23 330.93,2123.23 370.93,2123.23 410.93,2123.23 450.93,2123.23 490.93,2123.23 970.93,2123.23 1010.93,2123.23 1050.93,2123.23 1090.93,2123.23 1130.93,2123.23 1170.93,2123.23 1210.93,2123.23 1250.93,2123.23 1290.93,2123.23 70.93,2163.23 110.93,2163.23 150.93,2163.23 190.93,2163.23 230.93,2163.23 270.93,2163.23 310.93,2163.23 350.93,2163.23 630.93,2163.23 670.93,2163.23 710.93,2163.23 870.93,2163.23 990.93,2163.23 1030.93,2163.23 1070.93,2163.23 1110.93,2163.23 1150.93,2163.23 1190.93,2163.23 1230.93,2163.23 1270.93,2163.23 50.93,2203.23 90.93,2203.23 130.93,2203.23 170.93,2203.23 210.93,2203.23 250.93,2203.23 290.93,2203.23 330.93,2203.23 730.93,2203.23 890.93,2203.23 70.93,2243.23 110.93,2243.23 150.93,2243.23 190.93,2243.23 230.93,2243.23 270.93,2243.23 50.93,2283.23 210.93,2283.23 250.93,2283.23 650.93,2283.23 630.93,2323.23 50.93,2363.23 330.93,2363.23 450.93,2363.23 730.93,2363.23 770.93,2363.23 310.93,2403.23 350.93,2403.23 390.93,2403.23 430.93,2403.23 470.93,2403.23 510.93,2403.23 670.93,2403.23 710.93,2403.23 50.93,2443.23 290.93,2443.23 330.93,2443.23 370.93,2443.23 410.93,2443.23 450.93,2443.23 490.93,2443.23 530.93,2443.23 570.93,2443.23 610.93,2443.23 650.93,2443.23 690.93,2443.23 730.93,2443.23 770.93,2443.23 810.93,2443.23 1183.11,2467.64 70.93,2483.23 110.93,2483.23 150.93,2483.23 310.93,2483.23 350.93,2483.23 390.93,2483.23 430.93,2483.23 470.93,2483.23 510.93,2483.23 550.93,2483.23 590.93,2483.23 630.93,2483.23 670.93,2483.23 710.93,2483.23 750.93,2483.23 790.93,2483.23 1334.41,2507.83 50.93,2523.23 90.93,2523.23 130.93,2523.23 170.93,2523.23 1290.93,2523.23 70.93,2563.23 110.93,2563.23 150.93,2563.23 190.93,2563.23 1150.93,2563.23 1190.93,2563.23 50.93,2603.23 90.93,2603.23 130.93,2603.23 170.93,2603.23 210.93,2603.23 1130.93,2603.23 1170.93,2603.23 1210.93,2603.23 1290.93,2603.23 70.93,2643.23 110.93,2643.23 150.93,2643.23 190.93,2643.23 230.93,2643.23 270.93,2643.23 1110.93,2643.23 1150.93,2643.23 1190.93,2643.23 50.93,2683.23 90.93,2683.23 130.93,2683.23 170.93,2683.23 210.93,2683.23 250.93,2683.23 290.93,2683.23 330.93,2683.23 370.93,2683.23 410.93,2683.23 450.93,2683.23 490.93,2683.23 530.93,2683.23 570.93,2683.23 610.93,2683.23 650.93,2683.23 690.93,2683.23 730.93,2683.23 770.93,2683.23 810.93,2683.23 850.93,2683.23 890.93,2683.23 930.93,2683.23 970.93,2683.23 1010.93,2683.23 1050.93,2683.23 1090.93,2683.23 1130.93,2683.23 1170.93,2683.23 70.93,2723.23 110.93,2723.23 150.93,2723.23 190.93,2723.23 230.93,2723.23 270.93,2723.23 310.93,2723.23 350.93,2723.23 390.93,2723.23 430.93,2723.23 470.93,2723.23 510.93,2723.23 550.93,2723.23 590.93,2723.23 630.93,2723.23 670.93,2723.23 710.93,2723.23 750.93,2723.23 790.93,2723.23 830.93,2723.23 870.93,2723.23 910.93,2723.23 950.93,2723.23 990.93,2723.23 1030.93,2723.23 1070.93,2723.23 1110.93,2723.23 1150.93,2723.23 1190.93,2723.23 1230.93,2723.23 1270.93,2723.23
GND_11: C19.2 C37.2 C38.2 C39.2 C40.2 C41.2 C43.2 C44.2 C45.2 C46.2 C90.2 D7.1 D8.1 J7.5 J8.19 R51.1 U14.2 U14.3 U14.17 U15.A1 U31.2 | length 4409.5
  Top Layer w8: U14.3@988.66,4045.93 956.64,4013.92 v3(956.64,4000) 970.56,4000 U14.2@1002.58,4032.01
  Top Layer w25: v2(193.72,3666) v2(193.72,3750.39) ; R51.1@346.01,4084.6 376.81,4115.4 D8.1@503.11,4115.4 v2(503.11,4140) v2(503.11,4246.43) ; v2(501.02,3981.15) 503.11,3979.06 D7.1@503.11,3955.56 ; v2(749.99,3706) C37.2@749.99,3894.55 ; C90.2@981.02,4208.98 933.26,4208.98 v2(893.19,4249.04) 1222.07,4249.04 J7.5@1251.02,4278
  Bottom Layer w6: U15.A1@190.77,4038.54 191.41,4038.54 C45.2@249.01,4096.13
  Bottom Layer w12: C19.2@208.03,3802.08 211.02,3805.07 U31.2@211.02,3944.29
  Bottom Layer w25: v2(193.72,3666) 709.99,3666 v2(749.99,3706) 986.65,3706 1031.04,3750.39 1031.04,3944.08 C38.2@1029.94,3945.18 C39.2@992.36,3982.77 975.12,4000 v3(956.64,4000) 956.64,4020.21 C41.2@935.64,4041.22 ; v2(193.72,3750.39) 208.03,3764.7 C19.2@208.03,3802.08 ; C45.2@249.01,4096.13 C44.2@249.01,4150.92 249.01,4196.18 299.25,4246.43 v2(503.11,4246.43) 749.55,4246.43 v2(749.99,4245.99) 890.14,4245.99 v2(893.19,4249.04) 896.25,4245.99 C40.2@896.25,4080.59 C41.2@935.64,4041.22 ; v2(501.02,3981.15) 501.02,4137.91 v2(503.11,4140) ; J7.5@1251.02,4278 1333.02,4278 1371.02,4240 1371.02,4057.32
  Bottom Layer w50: v1@1339.02,3546 1339.02,3427.27 1387.95,3378.35 J8.19@1450,3378.35
  other v1: 48,3546 328,3546 368,3546 408,3546 448,3546 488,3546 528,3546 568,3546 608,3546 648,3546 688,3546 728,3546 768,3546 808,3546 848,3546 888,3546 928,3546 968,3546 1008,3546 1048,3546 1088,3546 1128,3546 1168,3546 1208,3546 1248,3546 1288,3546 1328,3546 1368,3546 1408,3546 68,3586 108,3586 308,3586 348,3586 388,3586 428,3586 468,3586 508,3586 548,3586 588,3586 628,3586 668,3586 708,3586 748,3586 788,3586 828,3586 868,3586 908,3586 948,3586 988,3586 1028,3586 1068,3586 1108,3586 1148,3586 1188,3586 1228,3586 1268,3586 1308,3586 1348,3586 1388,3586 48,3626 88,3626 128,3626 168,3626 208,3626 248,3626 288,3626 328,3626 368,3626 408,3626 448,3626 488,3626 528,3626 568,3626 608,3626 648,3626 688,3626 728,3626 768,3626 808,3626 848,3626 888,3626 928,3626 968,3626 1008,3626 1048,3626 1088,3626 1128,3626 1168,3626 1208,3626 1248,3626 1288,3626 1328,3626 68,3666 108,3666 148,3666 228,3666 268,3666 308,3666 348,3666 388,3666 428,3666 468,3666 508,3666 548,3666 588,3666 628,3666 668,3666 708,3666 748,3666 788,3666 828,3666 868,3666 908,3666 948,3666 988,3666 1028,3666 1068,3666 1108,3666 1148,3666 1188,3666 1228,3666 1268,3666 1308,3666 328,3706 368,3706 408,3706 448,3706 488,3706 528,3706 568,3706 608,3706 648,3706 688,3706 808,3706 848,3706 888,3706 928,3706 968,3706 1008,3706 1048,3706 1088,3706 1128,3706 1168,3706 1208,3706 1248,3706 1288,3706 108,3746 148,3746 128,3786 168,3786 328,3786 368,3786 408,3786 448,3786 568,3786 608,3786 648,3786 688,3786 728,3786 768,3786 808,3786 848,3786 888,3786 928,3786 1048,3786 1088,3786 1128,3786 1168,3786 1208,3786 1248,3786 1288,3786 108,3826 148,3826 348,3826 388,3826 428,3826 468,3826 548,3826 588,3826 628,3826 668,3826 708,3826 748,3826 788,3826 828,3826 868,3826 908,3826 948,3826 1188,3826 1308,3826 128,3866 328,3866 608,3866 648,3866 688,3866 308,3906 668,3906 708,3906 1308,3906 188,3986 228,3986 588,3986 1068,3986 1108,3986 1188,3986 1388,3986 1088,4026 1208,4026 1288,4026 1408,4026 388,4066 428,4066 668,4066 708,4066 1028,4066 1108,4066 1148,4066 1308,4066 1388,4066 408,4106 448,4106 648,4106 688,4106 848,4106 1008,4106 1048,4106 1168,4106 1408,4106 68,4146 348,4146 388,4146 428,4146 468,4146 548,4146 588,4146 628,4146 668,4146 708,4146 748,4146 1028,4146 1068,4146 1108,4146 1188,4146 1308,4146 1388,4146 48,4186 88,4186 1048,4186 1088,4186 1128,4186 1368,4186 68,4226 108,4226 148,4226 188,4226 228,4226 268,4226 868,4226 1028,4226 1068,4226 1108,4226 1148,4226 1188,4226 1228,4226 1308,4226 1348,4226 1388,4226 1428,4226 48,4266 88,4266 128,4266 168,4266 208,4266 248,4266 288,4266 328,4266 368,4266 408,4266 448,4266 568,4266 608,4266 648,4266 688,4266 808,4266 848,4266 928,4266 968,4266 1008,4266 1048,4266 1088,4266 1128,4266 1168,4266 1328,4266 1368,4266 68,4306 108,4306 148,4306 188,4306 228,4306 268,4306 308,4306 348,4306 388,4306 428,4306 468,4306 508,4306 548,4306 588,4306 628,4306 668,4306 708,4306 748,4306 788,4306 828,4306 868,4306 908,4306 948,4306 988,4306 1028,4306 1068,4306 1108,4306 1148,4306 1188,4306 1308,4306 1348,4306 1388,4306 48,4346 88,4346 128,4346 168,4346 208,4346 248,4346 288,4346 328,4346 368,4346 408,4346 448,4346 488,4346 528,4346 568,4346 608,4346 648,4346 688,4346 728,4346 768,4346 808,4346 848,4346 888,4346 928,4346 968,4346 1008,4346 1048,4346 1088,4346 1128,4346 1168,4346 1208,4346 1248,4346 1288,4346 1328,4346 1368,4346 1408,4346 1448,4346
NetC1_1: C1.1 R78.2 U21.2 | length 171.3
  Top Layer w12: U21.2@815.88,420.65 815.88,469.49 C1.1@795.39,489.98 833.23,527.83 R78.2@833.23,567.82
NetC2_1: C2.1 R80.2 U21.3 | length 196.9
  Top Layer w6: C2.1@735.59,489.98 764.13,461.44 776.16,461.44 796.19,441.41 U21.3@796.19,420.65
  Top Layer w10: C2.1@735.59,489.98 778,532.4 R80.2@778,567.82
NetC6_1: C6.1 C7.1 R4.1 U6.1 U6.2
NetC12_1: C12.1 C13.1 R9.1 U3.10 | length 225.2
  Top Layer w8: v2(1010.18,2277.25) 1026.34,2293.41 U3.10@1026.34,2314.13
  Bottom Layer w20: R9.1@930.18,2280.87 C12.1@930.18,2335.75 C13.1@990.18,2335.75 1010.18,2315.75 v2(1010.18,2277.25)
NetC14_1: C14.1 C15.1 R12.1 U3.9 | length 281.7
  Top Layer w8: C15.1@890,2261.89 954.42,2261.89 U3.9@1006.65,2314.13
  Top Layer w20: R12.1@754.68,2259.41 812.56,2259.41 C14.1@821.06,2250.9 879.01,2250.9 C15.1@890,2261.89
NetC15_2: C15.2 C17.1 R14.1 U3.8 | length 241.4
  Top Layer w8: C15.2@890,2324.89 966.23,2324.89 U3.8@981.06,2339.72
  Top Layer w20: R14.1@754.68,2329.41 812.56,2329.41 C17.1@821.06,2337.91 876.98,2337.91 C15.2@890,2324.89
NetC16_1: C16.1 C18.1 R16.2 RT2.2 U3.5 U3.7 | length 2274.2
  Top Layer w6: R16.2@843.97,2539.41 881.38,2539.41 891.06,2529.72 891.06,2480.9 C18.1@869.56,2459.41 869.56,2400.9 910.88,2359.59 981.06,2359.59 U3.7@981.06,2359.41 ; U3.5@981.06,2398.78 981.06,2449.41 1029.56,2497.91 C16.1@1029.56,2499.41
  Top Layer w12: v2(220,2395.83) 221.21,2394.61 228,2394.61 228,2466.34 301.06,2539.41 R16.2@843.97,2539.41 ; v2(221.06,2519.41) 251.06,2519.41 343.06,2611.41 1009.06,2611.41 1029.56,2590.9 C16.1@1029.56,2499.41
  Bottom Layer w12: v2(220,2395.83) 215.72,2391.55 RT2.2@196.85,2391.55 196.85,2495.2 v2(221.06,2519.41)
NetC16_2: C16.2 RT2.1 U3.4 | length 1373.1
  Top Layer w6: U3.4@1006.65,2424.37 1006.65,2445 1031.06,2469.41 1062.56,2469.41 C16.2@1092.56,2499.41
  Top Layer w12: v2(251.06,2569.41) 311.06,2629.41 1061.06,2629.41 1092.56,2597.91 C16.2@1092.56,2499.41
  Bottom Layer w12: RT2.1@196.85,2331.55 206.78,2331.55 251.06,2375.83 v2(251.06,2569.41)
NetC19_1: C19.1 R120.1 U31.4 | length 139.3
  Bottom Layer w25: U31.4@236.61,3855.71 255.76,3855.71 271.02,3840.45 C19.1@271.02,3802.08 251.48,3782.54 R120.1@251.48,3750
NetC21_1_1: C21_1.1 J37_1.2 R25_1.1 S1_1.2 U20_1.4 | length 1345.4
  Top Layer w6: S1_1.2@2160.39,387.33 2210.35,387.33 2287.56,310.12 2287.56,168.96 2306.52,150 2504.51,150 J37_1.2@2554.51,200 2554.51,298.14 R25_1.1@2556.38,300 C21_1.1@2484.72,300 2484.72,530.4 2328.52,686.59 2328.52,720.74 2284.84,764.41 U20_1.4@2254.88,764.41
NetC21_3_1: C21_3.1 J37_3.2 R25_3.1 S1_3.2 U20_3.4 | length 1345.4
  Top Layer w6: S1_3.2@2160.39,2001.5 2210.35,2001.5 2287.56,1924.29 2287.56,1783.13 2306.52,1764.17 2504.51,1764.17 J37_3.2@2554.51,1814.17 2554.51,1912.31 R25_3.1@2556.38,1914.17 C21_3.1@2484.72,1914.17 2484.72,2144.57 2328.52,2300.77 2328.52,2334.91 2284.84,2378.59 U20_3.4@2254.88,2378.59
NetC21_4_1: C21_4.1 J37_4.2 R25_4.1 S1_4.2 U20_4.4 | length 1345.4
  Top Layer w6: S1_4.2@2160.39,3615.67 2210.34,3615.67 2287.55,3538.46 2287.55,3397.3 2306.51,3378.34 2504.51,3378.34 J37_4.2@2554.51,3428.34 2554.51,3526.48 R25_4.1@2556.37,3528.34 C21_4.1@2484.71,3528.34 2484.71,3758.74 2328.51,3914.94 2328.51,3949.08 2284.84,3992.75 U20_4.4@2254.88,3992.75
NetC22_1_1: C22_1.1 U20_1.8 Y1_1.2 | length 273.9
  Top Layer w8: U20_1.8@2254.88,843.15 2299.44,843.15 2315.69,859.4 2315.69,917.6 2355.27,957.18 Y1_1.2@2366.22,957.18 2405.27,957.18 C22_1.1@2435.12,927.33
NetC22_3_1: C22_3.1 U20_3.8 Y1_3.2 | length 273.9
  Top Layer w8: U20_3.8@2254.88,2457.33 2299.44,2457.33 2315.69,2473.58 2315.69,2531.78 2355.27,2571.36 Y1_3.2@2366.22,2571.36 2405.27,2571.36 C22_3.1@2435.12,2541.5
NetC22_4_1: C22_4.1 U20_4.8 Y1_4.2 | length 273.9
  Top Layer w8: U20_4.8@2254.88,4071.5 2299.43,4071.5 2315.68,4087.75 2315.68,4145.95 2355.26,4185.52 Y1_4.2@2366.21,4185.52 2405.26,4185.52 C22_4.1@2435.11,4155.67
NetC23_1_1: C23_1.1 U20_1.7 Y1_1.1 | length 206
  Top Layer w8: U20_1.7@2254.88,823.47 2318.89,823.47 2354.18,858.76 Y1_1.1@2366.22,858.76 2408.28,858.76 C23_1.1@2435.12,885.6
